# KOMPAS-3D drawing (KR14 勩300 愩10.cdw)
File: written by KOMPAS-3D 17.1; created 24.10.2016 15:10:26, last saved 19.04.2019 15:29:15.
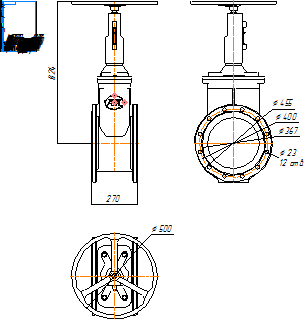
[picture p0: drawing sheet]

Sheet 1: A4, portrait

Title block, sheet 1: name: KR14 Ду300 Ру10; material: Внимание! Данный продукт является объектом авторского права ООО «Торговый Дом АДЛ». / Запрещается изменение, копирование, распространение / (в том числе путем копирования на другие сайты и ресурсы в Интернете) / или любое иное использование информации и объектов без предварительного / согласия правообладателя (ООО «Торговый Дом АДЛ»).; mass: 290,5; sheets: 1; organisation: ООО "Торговый дом АДЛ"; sheet format: A4; stored path: \\adlc.lan\data\АДЛ_ПКД\3D-модели\ADL production\Клиновые задвижки серии KR ГРАНАР\Клиновые задвижки KR14\kompas 2d\KR14 Ду300 Ру10.cdw

Views: Вид 1
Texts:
  Klimkovich
  ADL
Dimensions and other numbers on the sheet: 824; 270; 1:1; 1; 290,5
